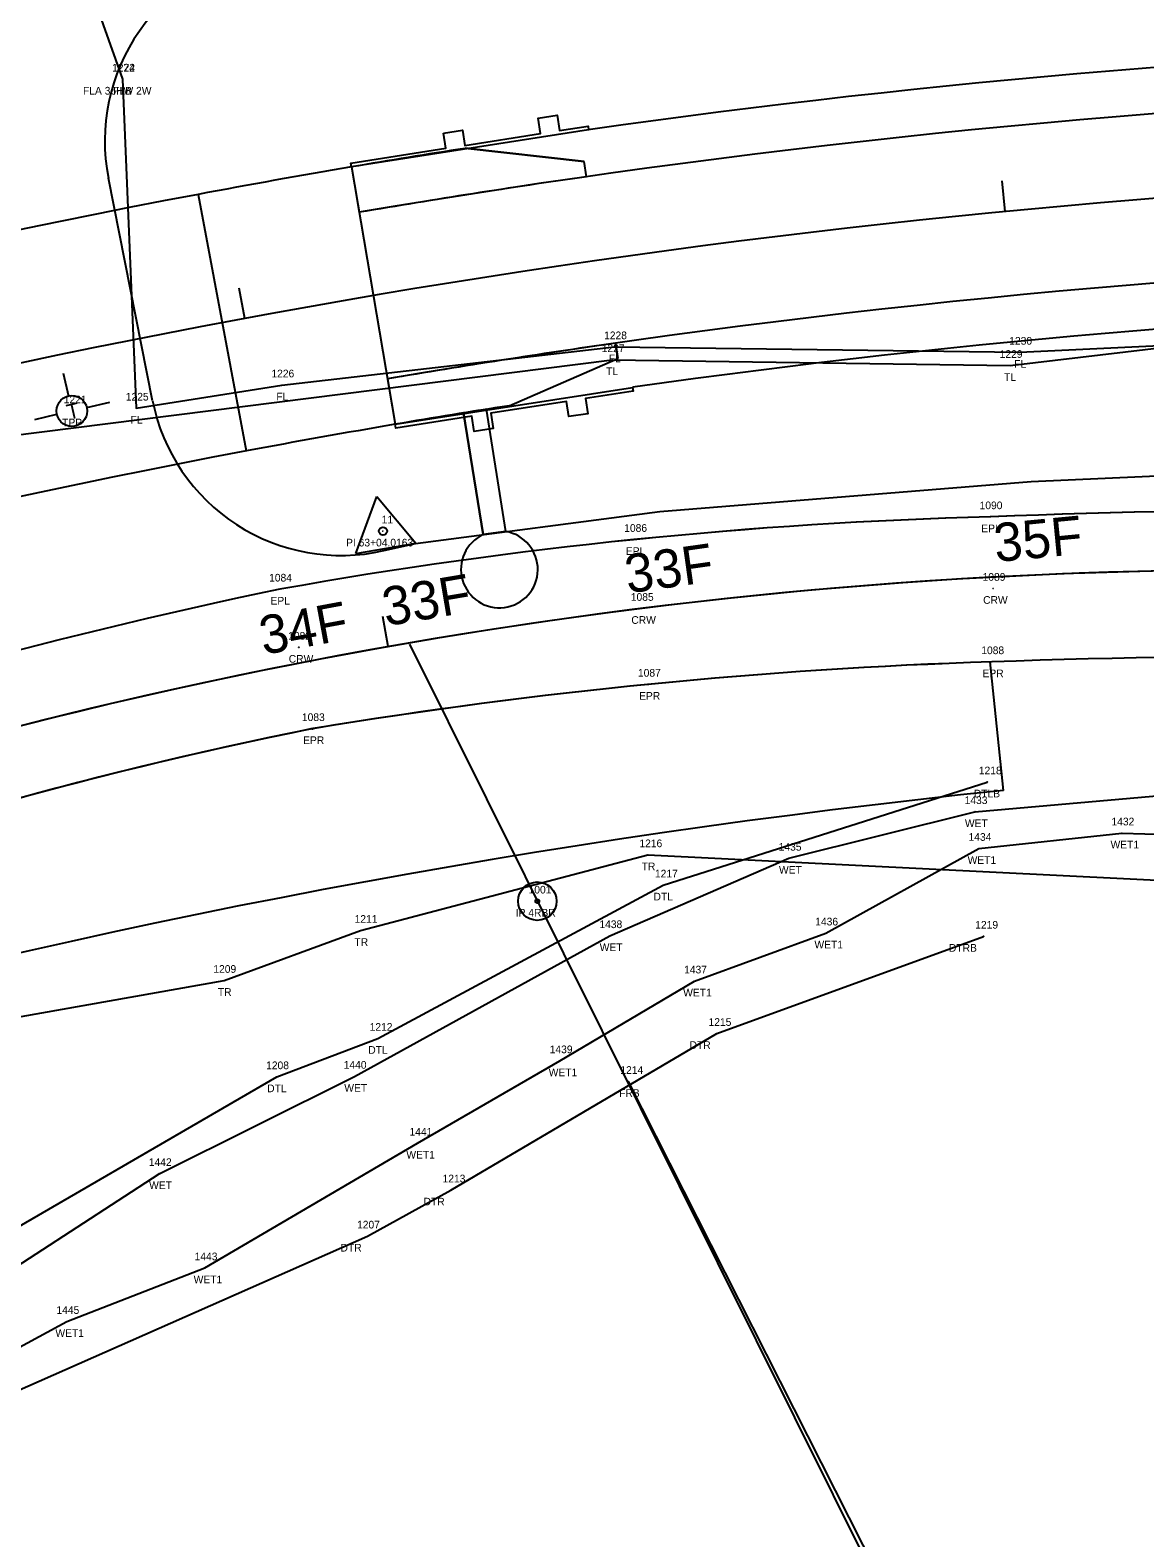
# Model space of a CAD drawing. Extents: x 1964982 to 1970452, y 1116335 to 1119906.
# Drawn here: x 1967933.9 to 1968079, y 1117805.4 to 1118001.8 of the extents above; entities that cross this region are included whole.
import ezdxf

# ---------------------------------------------------------------- set-up
doc = ezdxf.new("R2010")
doc.units = 0
for name, color, linetype in [('RD_EX_DV_Prop', 7, 'Continuous'), ('RD_EX_DV_Prop_txCode', 7, 'Continuous'), ('RD_EX_DV_PropPin', 7, 'Continuous'), ('RD_EX_Fence_Other', 7, 'Continuous'), ('RD_EX_Fence_Other_txCode', 7, 'Continuous'), ('RD_EX_H2O', 7, 'Continuous'), ('RD_EX_H2O_txCode', 7, 'Continuous'), ('RD_EX_H2O_WetLd', 7, 'Continuous'), ('RD_EX_H2O_WetLd_txCode', 7, 'Continuous'), ('RD_EX_Road', 7, 'Continuous'), ('RD_EX_Road_txCode', 7, 'Continuous'), ('RD_EX_RW', 7, 'Continuous'), ('RD_EX_UT', 7, 'Continuous'), ('RD_EX_UT_txCode', 7, 'Continuous'), ('RD_EX_VEG', 7, 'Continuous'), ('RD_EX_VEG_txCode', 7, 'Continuous'), ('RD_HC_CL', 7, 'Continuous'), ('RD_HC_CL_Rel', 7, 'Continuous'), ('RD_HC_Data', 7, 'Continuous'), ('RD_HC_Data_Tic', 7, 'Continuous'), ('RD_HC_Data_Tic_Rel', 7, 'Continuous'), ('RD_HC_txCode', 7, 'Continuous'), ('RD_PD_Bridge', 7, 'Continuous'), ('RD_PD_CstnLmt', 7, 'Continuous'), ('RD_PD_Final_TrvlWay', 7, 'Continuous'), ('RD_PD_PaveDit', 7, 'Continuous'), ('RD_PD_PaveShd', 7, 'Continuous'), ('RD_PD_RW', 7, 'Continuous'), ('RD_PD_TX_CstnLmt', 7, 'Continuous'), ('RD_QTY_GR', 7, 'Continuous'), ('RD_SMD_Locator', 7, 'Continuous'), ('RD_SMD_Misc', 7, 'Continuous')]:
    doc.layers.add(name, color=color, linetype=linetype)

msp = doc.modelspace()

# ---------------------------------------------------------------- linework, layer by layer
at = {"layer": 'RD_EX_DV_Prop'}
msp.add_line((1967983.28, 1117921.77), (1968204.25, 1117478.1), dxfattribs=at)
msp.add_arc((1968094.39, 1117277.53), 653.93, 87.72663, 109.21172, dxfattribs=at)
at = {"layer": 'RD_EX_DV_PropPin'}
for radius in [2.5, 0.25]:
    msp.add_circle((1967999.94, 1117888.32), radius, dxfattribs=at)
at = {"layer": 'RD_EX_Fence_Other'}
msp.add_line((1968047.83, 1117793.64), (1968011.81, 1117864.83), dxfattribs=at)
for points in [[(1967920.92, 1118368.66), (1967937.87, 1118342.4), (1967954.81, 1118301.31), (1967965.67, 1118250.56), (1967963.61, 1118188.09), (1967935.71, 1118144.56), (1967926.43, 1118106.38), (1967926.25, 1118051.25), (1967941.61, 1118007.63), (1967945.93, 1117995.37)], [(1967945.93, 1117995.37), (1967947.71, 1117952.52), (1967966.69, 1117955.54), (1968009.98, 1117960.51), (1968062.77, 1117959.8), (1968105.6, 1117961.86), (1968158.55, 1117958.33), (1968214.15, 1117955.95), (1968422.33, 1117947.89), (1968537.53, 1117942.88)]]:
    msp.add_lwpolyline(points, dxfattribs=at)
at = {"layer": 'RD_EX_H2O'}
for points in [[(1967869.1, 1117825.19), (1967872.82, 1117824.49), (1967892.16, 1117820.53), (1967923.08, 1117840.53), (1967966.02, 1117865.44), (1967979.17, 1117870.44), (1968016.32, 1117890.41), (1968058.49, 1117903.84)], [(1967873.55, 1117813.3), (1967887.27, 1117810.69), (1967931.74, 1117824.33), (1967977.85, 1117844.69), (1967988.67, 1117850.69), (1968023.3, 1117871.08), (1968058.02, 1117883.74)]]:
    msp.add_lwpolyline(points, dxfattribs=at)
at = {"layer": 'RD_EX_H2O_WetLd'}
for points in [[(1967871.9, 1117823.22), (1967882.77, 1117820.95), (1967892.49, 1117817.57), (1967903.12, 1117821.47), (1967929.31, 1117838.9), (1967950.71, 1117852.83), (1967976.12, 1117865.5), (1968009.37, 1117883.81), (1968032.7, 1117893.9), (1968056.92, 1117899.97), (1968087.96, 1117902.71), (1968127.85, 1117903.36), (1968147.64, 1117899.29), (1968163.17, 1117903.04), (1968190.62, 1117902.21), (1968208.25, 1117901.82), (1968234.81, 1117900.5)], [(1967873.8, 1117813.35), (1967880.72, 1117811.81), (1967886.54, 1117810.11), (1967895.47, 1117810.58), (1967906.3, 1117816.05), (1967938.67, 1117833.57), (1967956.67, 1117840.55), (1967984.36, 1117856.79), (1968002.89, 1117867.52), (1968020.4, 1117877.91), (1968037.49, 1117884.16), (1968057.43, 1117895.18), (1968076.04, 1117897.19), (1968096.98, 1117896.55), (1968127.56, 1117896.46), (1968147.25, 1117896.52), (1968165.45, 1117895.9), (1968184.88, 1117896.85), (1968203.56, 1117897.42), (1968232.27, 1117895.94)]]:
    msp.add_lwpolyline(points, dxfattribs=at)
at = {"layer": 'RD_EX_Road'}
for centre, radius, start, end in [((1968111.4, 1116608.55), 1330.85, 87.96323, 92.25904), ((1968075.08, 1117320.65), 617.93, 91.49649, 100.12953), ((1968104.91, 1117261.07), 682.09, 101.71624, 109.63962), ((1968080.71, 1117246.52), 673.31, 91.83702, 99.40571), ((1968107.56, 1116504.27), 1416.05, 87.91148, 91.95976), ((1968080.62, 1117362.97), 558.74, 101.3479, 110.7006)]:
    msp.add_arc(centre, radius, start, end, dxfattribs=at)
at = {"layer": 'RD_EX_RW'}
for points in [[(1968058.98, 1117938.37), (1968058.94, 1117938.37), (1968058.91, 1117938.37)], [(1967970.6, 1117910.76), (1967970.68, 1117910.78), (1967970.76, 1117910.79)]]:
    msp.add_lwpolyline(points, dxfattribs=at)
for centre, radius, start, end in [((1968111.4, 1116608.55), 1330.85, 87.96323, 92.25762), ((1968075.08, 1117320.65), 617.93, 91.49955, 100.12953), ((1968104.91, 1117261.07), 682.09, 101.71624, 109.63962), ((1968080.71, 1117246.52), 673.31, 91.83702, 99.39844), ((1968107.56, 1116504.27), 1416.05, 87.91148, 91.95976), ((1968080.62, 1117362.97), 558.74, 101.3567, 110.7006)]:
    msp.add_arc(centre, radius, start, end, dxfattribs=at)
at = {"layer": 'RD_EX_UT'}
for p, q in [((1967938.2, 1117957.1), (1967938.89, 1117954.11)), ((1967941.29, 1117952.62), (1967944.28, 1117953.31)), ((1967934.53, 1117951.07), (1967937.39, 1117951.73))]:
    msp.add_line(p, q, dxfattribs=at)
msp.add_circle((1967939.34, 1117952.16), 2, dxfattribs=at)
at = {"layer": 'RD_EX_VEG'}
for points in [[(1967422.03, 1117809.72), (1967453.38, 1117748.92), (1967559.8, 1117796.17), (1967844.47, 1117917.07), (1967917.86, 1117947.25), (1968009.67, 1117958.84), (1968061.48, 1117958.08), (1968105.8, 1117963.33), (1968158.86, 1117956.79), (1968212.37, 1117954.08), (1968423.16, 1117946.63), (1968536.42, 1117942.26)], [(1967303.54, 1117601.01), (1967338.99, 1117640.22), (1967353.28, 1117654.56), (1967394.76, 1117667.24), (1967484.61, 1117707.66), (1967711.58, 1117796.67), (1967890.09, 1117864.21), (1967929.29, 1117872.68), (1967959.15, 1117877.99), (1967976.93, 1117884.5), (1968014.32, 1117894.35), (1968104.14, 1117889.87), (1968155.31, 1117895.48), (1968209.85, 1117895.88), (1968320.55, 1117893.51), (1968423.04, 1117892.22), (1968529.15, 1117876.96)]]:
    msp.add_lwpolyline(points, dxfattribs=at)
at = {"layer": 'RD_HC_CL'}
msp.add_arc((1968094.39, 1117277.53), 653.93, 87.72663, 111.99584, dxfattribs=at)
at = {"layer": 'RD_HC_CL_Rel'}
msp.add_arc((1968170.83, 1116837.51), 1145.92, 84.66612, 115.04633, dxfattribs=at)
at = {"layer": 'RD_HC_Data'}
for p, q in [((1967976.32, 1117933.58), (1967979.05, 1117941.04)), ((1967979.05, 1117941.04), (1967984.14, 1117934.94)), ((1967976.32, 1117933.58), (1967984.14, 1117934.94))]:
    msp.add_line(p, q, dxfattribs=at)
msp.add_circle((1967979.84, 1117936.52), 0.529, dxfattribs=at)
at = {"layer": 'RD_HC_Data_Tic'}
msp.add_line((1967980.52, 1117921.47), (1967979.82, 1117925.41), dxfattribs=at)
at = {"layer": 'RD_HC_Data_Tic_Rel'}
for p, q in [((1968060.85, 1117978.14), (1968060.47, 1117982.12)), ((1967961.86, 1117964.21), (1967961.13, 1117968.15))]:
    msp.add_line(p, q, dxfattribs=at)
at = {"layer": 'RD_PD_Bridge'}
msp.add_line((1967955.77, 1117980.37), (1967962.05, 1117946.95), dxfattribs=at)
for radius in [1162.92, 1128.92]:
    msp.add_arc((1968170.83, 1116837.51), radius, 100.65724, 115.04633, dxfattribs=at)
at = {"layer": 'RD_PD_CstnLmt'}
for p, q in [((1967949.84, 1117953.48), (1967944.1, 1117982.47)), ((1968064.24, 1117942.97), (1968112.64, 1117945.12)), ((1968015.87, 1117939.09), (1968064.24, 1117942.97)), ((1967984.09, 1117934.92), (1968015.87, 1117939.09)), ((1967979.94, 1117933.97), (1967984.09, 1117934.92))]:
    msp.add_line(p, q, dxfattribs=at)
for centre, start, end in [((1967968.63, 1117987.33), 98.9687, 191.2007), ((1967974.37, 1117958.34), 191.2007, 282.8807)]:
    msp.add_arc(centre, 25, start, end, dxfattribs=at)
at = {"layer": 'RD_PD_Final_TrvlWay'}
msp.add_line((1967975.74, 1117983.95), (1967981.45, 1117950.43), dxfattribs=at)
for radius, start, end in [(1156.92, 84.66612, 99.65724), (1162.92, 99.65724, 100.65724), (1134.92, 84.66612, 99.65724), (1128.92, 99.65724, 100.65724)]:
    msp.add_arc((1968170.83, 1116837.51), radius, start, end, dxfattribs=at)
at = {"layer": 'RD_PD_PaveDit'}
for p, q in [((1967995.84, 1117936.46), (1967993.31, 1117952.38)), ((1967995.84, 1117936.46), (1967993.31, 1117952.38)), ((1967992.9, 1117936.07), (1967990.34, 1117951.91)), ((1967990.34, 1117951.91), (1967992.9, 1117936.07)), ((1967995.84, 1117936.46), (1967992.9, 1117936.07)), ((1967992.9, 1117936.07), (1967995.84, 1117936.46))]:
    msp.add_line(p, q, dxfattribs=at)
for centre, radius, start, end in [((1968170.83, 1116837.51), 1128.92, 99.04733, 99.19981), ((1967995, 1117931.53), 5, 114.7487, 80.3172), ((1967995, 1117931.53), 5, 80.2814, 80.3172)]:
    msp.add_arc(centre, radius, start, end, dxfattribs=at)
at = {"layer": 'RD_PD_PaveShd'}
for p, q in [((1967990.53, 1117986.37), (1968006.05, 1117984.65)), ((1968006.05, 1117984.65), (1967990.53, 1117986.37)), ((1967975.74, 1117983.95), (1967976.75, 1117978.03)), ((1968006.34, 1117982.67), (1968006.05, 1117984.65)), ((1968006.34, 1117982.67), (1968006.05, 1117984.65)), ((1968010.13, 1117960.99), (1968010.41, 1117959.01)), ((1968010.41, 1117959.01), (1968010.13, 1117960.99)), ((1967996.27, 1117952.85), (1968010.41, 1117959.01)), ((1967996.27, 1117952.85), (1968010.41, 1117959.01)), ((1967980.44, 1117956.34), (1967981.45, 1117950.43))]:
    msp.add_line(p, q, dxfattribs=at)
for radius, start in [(1162.92, 98.91924), (1162.92, 98.91924), (1156.92, 98.17407), (1134.92, 98.14003), (1128.92, 98.89485), (1128.92, 98.89485)]:
    msp.add_arc((1968170.83, 1116837.51), radius, start, 99.65724, dxfattribs=at)
at = {"layer": 'RD_PD_RW'}
msp.add_line((1968060.61, 1117902.74), (1968058.88, 1117919.48), dxfattribs=at)
for radius in [1220.92, 1070.92]:
    msp.add_arc((1968170.83, 1116837.51), radius, 95.90724, 115.04633, dxfattribs=at)
at = {"layer": 'RD_QTY_GR'}
for points in [[(1967987.71, 1117988.35), (1967990.18, 1117988.74), (1967990.49, 1117986.75), (1968000.37, 1117988.3), (1968000.06, 1117990.28), (1968002.53, 1117990.67), (1968002.84, 1117988.68), (1968006.54, 1117989.26), (1968006.62, 1117988.78), (1967975.74, 1117983.95), (1967975.67, 1117984.43), (1967988.02, 1117986.37)], [(1967981.45, 1117950.43), (1968012.32, 1117955.24), (1968012.4, 1117954.76), (1968006.23, 1117953.8), (1968006.53, 1117951.81), (1968004.06, 1117951.43), (1968003.75, 1117953.41), (1967993.87, 1117951.87), (1967994.18, 1117949.89), (1967991.71, 1117949.5), (1967991.4, 1117951.48), (1967981.52, 1117949.94)]]:
    msp.add_lwpolyline(points, close=True, dxfattribs=at)
for radius, end in [(1162.92, 98.1201), (1128.92, 98.06898)]:
    msp.add_arc((1968170.83, 1116837.51), radius, 84.66612, end, dxfattribs=at)
at = {"layer": 'RD_SMD_Locator'}
for centre in [(1967945.93, 1117995.37), (1967945.93, 1117995.37), (1968009.98, 1117960.51), (1968009.67, 1117958.84), (1968062.77, 1117959.8), (1968061.48, 1117958.08), (1967966.69, 1117955.54), (1967947.71, 1117952.52), (1968058.94, 1117938.37), (1967979.84, 1117936.52), (1968012.66, 1117935.42), (1967966.4, 1117928.95), (1968059.29, 1117929.05), (1968013.49, 1117926.44), (1967968.89, 1117921.38), (1968059.13, 1117919.49), (1968014.42, 1117916.56), (1967970.68, 1117910.78), (1968058.49, 1117903.84), (1968056.92, 1117899.97), (1968076.04, 1117897.19), (1968014.32, 1117894.35), (1968032.7, 1117893.9), (1968057.43, 1117895.18), (1968016.32, 1117890.41), (1967976.93, 1117884.5), (1968009.37, 1117883.81), (1968037.49, 1117884.16), (1968058.02, 1117883.74), (1967959.15, 1117877.99), (1968020.4, 1117877.91), (1967979.17, 1117870.44), (1968023.3, 1117871.08), (1968002.89, 1117867.52), (1967966.02, 1117865.44), (1967976.12, 1117865.5), (1968011.81, 1117864.83), (1967984.36, 1117856.79), (1967950.71, 1117852.83), (1967988.67, 1117850.69), (1967977.85, 1117844.69), (1967956.67, 1117840.55), (1967938.67, 1117833.57)]:
    msp.add_circle(centre, 0.001, dxfattribs=at)

# ---------------------------------------------------------------- texts
at = {"layer": 'RD_EX_DV_Prop_txCode'}
for s, p in [('1001', (1967998.8, 1117889.32)), ('IP 4RBR', (1967997.13, 1117886.32))]:
    msp.add_text(s, height=1, dxfattribs=at).set_placement(p)
at = {"layer": 'RD_EX_Fence_Other_txCode'}
for s, p in [('1224', (1967944.58, 1117996.37)), ('1272', (1967944.58, 1117996.37)), ('FLA 36HW 2W', (1967940.79, 1117993.37)), ('FLB', (1967944.72, 1117993.37)), ('1228', (1968008.63, 1117961.51)), ('1230', (1968061.38, 1117960.8)), ('FL', (1968009.24, 1117958.51)), ('FL', (1968062.03, 1117957.8)), ('1226', (1967965.32, 1117956.54)), ('1225', (1967946.36, 1117953.52)), ('FL', (1967965.96, 1117953.54)), ('FL', (1967946.98, 1117950.52)), ('1214', (1968010.75, 1117865.83)), ('FRB', (1968010.59, 1117862.83))]:
    msp.add_text(s, height=1, dxfattribs=at).set_placement(p)
at = {"layer": 'RD_EX_H2O_txCode'}
for s, p in [('1218', (1968057.42, 1117904.84)), ('DTLB', (1968056.77, 1117901.84)), ('1217', (1968015.25, 1117891.41)), ('DTL', (1968015.07, 1117888.41)), ('1219', (1968056.95, 1117884.74)), ('DTRB', (1968053.53, 1117881.74)), ('1212', (1967978.11, 1117871.44)), ('1215', (1968022.23, 1117872.08)), ('DTR', (1968019.76, 1117869.08)), ('DTL', (1967977.93, 1117868.44)), ('1208', (1967964.63, 1117866.44)), ('DTL', (1967964.77, 1117863.44)), ('1213', (1967987.6, 1117851.69)), ('DTR', (1967985.13, 1117848.69)), ('1207', (1967976.47, 1117845.69)), ('DTR', (1967974.32, 1117842.69))]:
    msp.add_text(s, height=1, dxfattribs=at).set_placement(p)
at = {"layer": 'RD_EX_H2O_WetLd_txCode'}
for s, p in [('1433', (1968055.57, 1117900.97)), ('WET', (1968055.61, 1117897.97)), ('1432', (1968074.69, 1117898.19)), ('1435', (1968031.36, 1117894.9)), ('1434', (1968056.08, 1117896.18)), ('WET1', (1968074.57, 1117895.19)), ('WET1', (1968055.96, 1117893.18)), ('WET', (1968031.4, 1117891.9)), ('1438', (1968008.02, 1117884.81)), ('1436', (1968036.12, 1117885.16)), ('WET', (1968008.06, 1117881.81)), ('WET1', (1968036.02, 1117882.16)), ('1437', (1968019.05, 1117878.91)), ('WET1', (1968018.93, 1117875.91)), ('1439', (1968001.55, 1117868.52)), ('1440', (1967974.73, 1117866.5)), ('WET1', (1968001.42, 1117865.52)), ('WET', (1967974.81, 1117863.5)), ('1441', (1967983.3, 1117857.79)), ('1442', (1967949.36, 1117853.83)), ('WET1', (1967982.89, 1117854.79)), ('WET', (1967949.4, 1117850.83)), ('1443', (1967955.32, 1117841.55)), ('WET1', (1967955.2, 1117838.55)), ('1445', (1967937.33, 1117834.57)), ('WET1', (1967937.2, 1117831.57))]:
    msp.add_text(s, height=1, dxfattribs=at).set_placement(p)
at = {"layer": 'RD_EX_Road_txCode'}
for s, p in [('1090', (1968057.52, 1117939.37)), ('1086', (1968011.25, 1117936.42)), ('EPL', (1968057.74, 1117936.37)), ('EPL', (1968011.46, 1117933.42)), ('1084', (1967965.02, 1117929.95)), ('EPL', (1967965.2, 1117926.95)), ('1088', (1968057.74, 1117920.49)), ('1087', (1968013.04, 1117917.56)), ('EPR', (1968057.9, 1117917.49)), ('EPR', (1968013.19, 1117914.56)), ('1083', (1967969.29, 1117911.78)), ('EPR', (1967969.45, 1117908.78))]:
    msp.add_text(s, height=1, dxfattribs=at).set_placement(p)
at = {"layer": 'RD_EX_UT'}
msp.add_text('T', height=2, rotation=12.9436, dxfattribs=at).set_placement((1967938.92, 1117950.99))
at = {"layer": 'RD_EX_UT_txCode'}
for s, p in [('1221', (1967938.28, 1117953.16)), ('TPP', (1967938.07, 1117950.16))]:
    msp.add_text(s, height=1, dxfattribs=at).set_placement(p)
at = {"layer": 'RD_EX_VEG_txCode'}
for s, p in [('1227', (1968008.32, 1117959.84)), ('1229', (1968060.13, 1117959.08)), ('TL', (1968008.9, 1117956.84)), ('TL', (1968060.71, 1117956.08)), ('1216', (1968013.23, 1117895.35)), ('TR', (1968013.52, 1117892.35)), ('1211', (1967976.15, 1117885.5)), ('TR', (1967976.13, 1117882.5)), ('1209', (1967957.76, 1117878.99)), ('TR', (1967958.35, 1117875.99))]:
    msp.add_text(s, height=1, dxfattribs=at).set_placement(p)
at = {"layer": 'RD_HC_txCode'}
for s, p in [('11', (1967979.67, 1117937.52)), ('PI 63+04.0163', (1967975.04, 1117934.52))]:
    msp.add_text(s, height=1, dxfattribs=at).set_placement(p)
at = {"layer": 'RD_PD_TX_CstnLmt'}
for s, rotation, p in [('35F', 5.5072, (1968059.62, 1117932.48)), ('33F', 8.0072, (1968011.71, 1117928.4)), ('33F', 9.6572, (1967980.23, 1117924.12)), ('34F', 10.5072, (1967964.28, 1117920.38))]:
    msp.add_text(s, height=5, rotation=rotation, dxfattribs=at).set_placement(p)
at = {"layer": 'RD_SMD_Misc'}
for s, p in [('1089', (1968057.91, 1117930.05)), ('1085', (1968012.11, 1117927.44)), ('CRW', (1968057.98, 1117927.05)), ('CRW', (1968012.18, 1117924.44)), ('1082', (1967967.5, 1117922.38)), ('CRW', (1967967.58, 1117919.38))]:
    msp.add_text(s, height=1, dxfattribs=at).set_placement(p)

doc.saveas('drawing.dxf')
